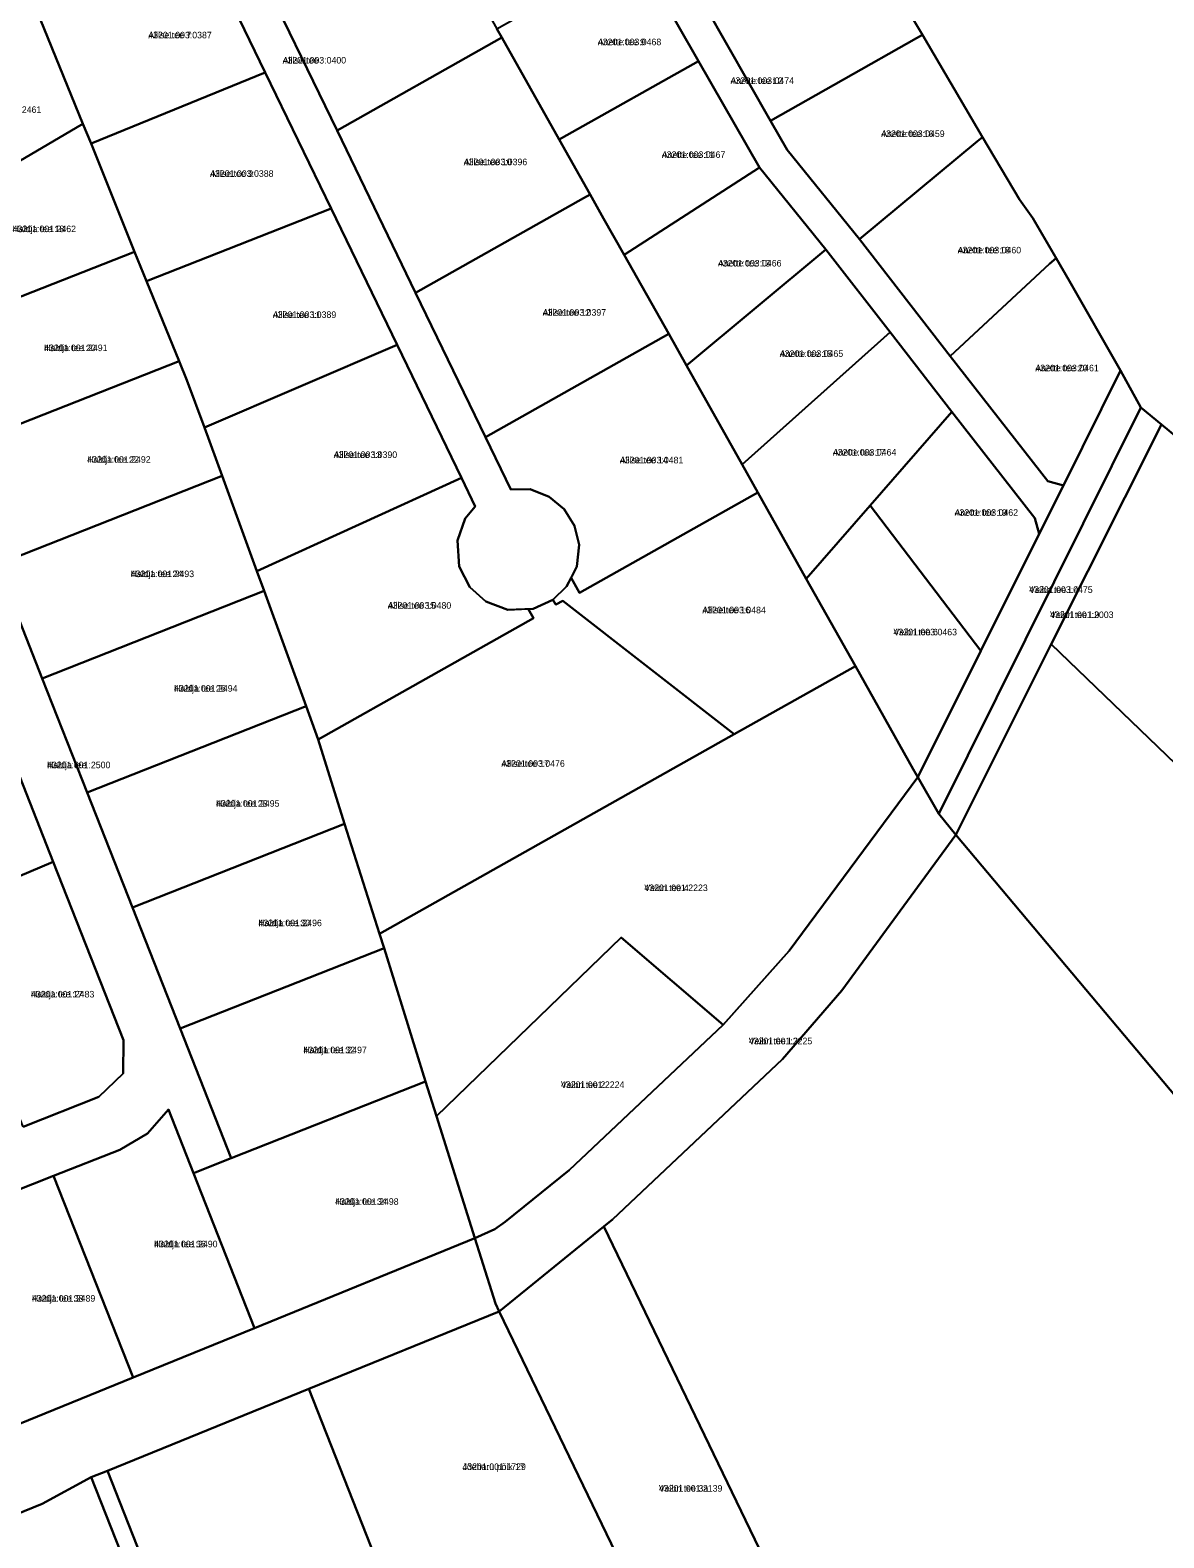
# Model space of a CAD drawing. Extents: x 661852 to 683758, y 6469495 to 6482657.
# Drawn here: x 663455 to 663714.1, y 6470005.7 to 6470350.3 of the extents above; entities that cross this region are included whole.
import ezdxf

# ---------------------------------------------------------------- set-up
doc = ezdxf.new("R2010")
doc.units = 0
for name, color, linetype in [('L_AADRESS', 7, 'Continuous'), ('PIIR', 7, 'Continuous'), ('TUNNUS', 7, 'Continuous')]:
    doc.layers.add(name, color=color, linetype=linetype)

msp = doc.modelspace()

# ---------------------------------------------------------------- linework, layer by layer
at = {"layer": 'PIIR'}
for points in [[(663551.97, 6470463.36), (663549.87, 6470459.62), (663563.18, 6470436.31), (663579.58, 6470407.67), (663594.36, 6470381.56), (663609.37, 6470355.58), (663624.26, 6470329.54), (663628.03, 6470322.94), (663644.55, 6470302.52), (663665.29, 6470275.78), (663687.59, 6470247.16), (663691.18, 6470246.17), (663685.65, 6470235.14), (663684.65, 6470238.71), (663665.72, 6470263.06), (663651.61, 6470281.22), (663636.88, 6470300.17), (663621.72, 6470318.87), (663607.79, 6470343.17), (663593.4, 6470368.36), (663579.26, 6470393.1), (663564.86, 6470418.28), (663551.46, 6470441.72), (663539.03, 6470463.45)], [(663506.1, 6470366.7), (663539.83, 6470385.7), (663541.42, 6470386.6), (663547.74, 6470375.39), (663561.73, 6470350.56), (663562.85, 6470348.57), (663561.11, 6470347.58), (663525.17, 6470327.33)], [(663643.69, 6470375.01), (663654.36, 6470356.98), (663658.96, 6470349.18), (663657.6, 6470348.41), (663624.26, 6470329.54), (663609.37, 6470355.58), (663642.33, 6470374.24)], [(663455.55, 6470357.09), (663493.33, 6470372.44), (663508.77, 6470340.56), (663468.95, 6470324.34), (663467.07, 6470328.89)], [(663593.4, 6470368.36), (663607.79, 6470343.17), (663577.71, 6470326.26), (663575.97, 6470325.28), (663562.85, 6470348.57), (663561.73, 6470350.56), (663563.48, 6470351.54)], [(663413.86, 6470306.25), (663405.06, 6470316.93), (663438.2, 6470348.65), (663453.21, 6470363), (663455.55, 6470357.09), (663467.07, 6470328.89), (663417.42, 6470299.67)], [(663525.17, 6470327.33), (663561.11, 6470347.58), (663562.85, 6470348.57), (663575.97, 6470325.28), (663583.04, 6470312.73), (663581.47, 6470311.85), (663543.13, 6470290.24)], [(663658.96, 6470349.18), (663672.73, 6470325.82), (663671.58, 6470324.87), (663644.55, 6470302.52), (663628.03, 6470322.94), (663624.26, 6470329.54), (663657.6, 6470348.41)], [(663607.79, 6470343.17), (663621.72, 6470318.87), (663590.81, 6470298.94), (663586.04, 6470307.23), (663583.04, 6470312.73), (663575.97, 6470325.28), (663577.71, 6470326.26)], [(663478.9, 6470299.63), (663468.95, 6470324.34), (663508.77, 6470340.56), (663523.81, 6470309.49), (663481.61, 6470292.92)], [(663424.41, 6470286.73), (663417.42, 6470299.67), (663467.07, 6470328.89), (663468.95, 6470324.34), (663478.9, 6470299.63), (663427.33, 6470279.31)], [(663672.73, 6470325.82), (663681.15, 6470311.54), (663684.21, 6470307.28), (663689.5, 6470298.18), (663688.03, 6470296.82), (663665.29, 6470275.78), (663644.55, 6470302.52), (663671.58, 6470324.87)], [(663621.72, 6470318.87), (663636.88, 6470300.17), (663605.06, 6470273.63), (663601.01, 6470280.83), (663590.81, 6470298.94)], [(663543.13, 6470290.24), (663581.47, 6470311.85), (663583.04, 6470312.73), (663586.04, 6470307.23), (663590.81, 6470298.94), (663601.01, 6470280.83), (663559.1, 6470257.26)], [(663489.08, 6470274.65), (663481.61, 6470292.92), (663523.81, 6470309.49), (663538.9, 6470278.33), (663494.85, 6470259.49), (663490.85, 6470270.27)], [(663437.22, 6470254.19), (663427.33, 6470279.31), (663478.9, 6470299.63), (663481.61, 6470292.92), (663489.08, 6470274.65)], [(663636.88, 6470300.17), (663651.61, 6470281.22), (663617.77, 6470251.01), (663605.06, 6470273.63)], [(663689.5, 6470298.18), (663692.54, 6470292.88), (663704.26, 6470272.48), (663691.18, 6470246.17), (663687.59, 6470247.16), (663665.29, 6470275.78), (663688.03, 6470296.82)], [(663559.1, 6470257.26), (663601.01, 6470280.83), (663605.06, 6470273.63), (663617.77, 6470251.01), (663621.37, 6470244.61), (663580.57, 6470221.67), (663578.65, 6470225.07), (663579.97, 6470227.66), (663580.5, 6470232.6), (663579.46, 6470236.96), (663577.11, 6470240.76), (663573.66, 6470243.64), (663569.28, 6470245.33), (663564.89, 6470245.32)], [(663651.61, 6470281.22), (663665.72, 6470263.06), (663647, 6470241.61), (663632.41, 6470224.85), (663621.37, 6470244.61), (663617.77, 6470251.01)], [(663498.91, 6470248.41), (663494.85, 6470259.49), (663538.9, 6470278.33), (663553.63, 6470247.92), (663506.83, 6470226.65)], [(663447.51, 6470228.15), (663437.22, 6470254.19), (663489.08, 6470274.65), (663490.85, 6470270.27), (663494.85, 6470259.49), (663498.91, 6470248.41)], [(663704.26, 6470272.48), (663708.85, 6470264.03), (663662.69, 6470171.12), (663657.88, 6470179.51), (663672.32, 6470208.4), (663685.65, 6470235.14), (663691.18, 6470246.17)], [(663666.62, 6470166.36), (663662.69, 6470171.12), (663708.85, 6470264.03), (663713.6, 6470260.11), (663688.4, 6470209.95)], [(663665.72, 6470263.06), (663684.65, 6470238.71), (663685.65, 6470235.14), (663672.32, 6470208.4), (663647, 6470241.61)], [(663769.59, 6470131.79), (663688.4, 6470209.95), (663713.6, 6470260.11), (663813.93, 6470177.18)], [(663457.77, 6470202.1), (663447.51, 6470228.15), (663498.91, 6470248.41), (663506.83, 6470226.65), (663508.52, 6470222.1)], [(663518.08, 6470195.78), (663508.52, 6470222.1), (663506.83, 6470226.65), (663553.63, 6470247.92), (663556.77, 6470241.43), (663554.46, 6470238.68), (663552.68, 6470233.66), (663553.08, 6470227.72), (663555.53, 6470222.94), (663559.19, 6470219.67), (663564.2, 6470217.79), (663568.87, 6470217.99), (663570.06, 6470215.88), (663520.86, 6470188.15)], [(663578.65, 6470225.07), (663580.57, 6470221.67), (663621.37, 6470244.61), (663632.41, 6470224.85), (663643.63, 6470204.94), (663615.9, 6470189.37), (663576.81, 6470219.87), (663575.2, 6470218.97), (663574.46, 6470220.06), (663577.64, 6470223.08)], [(663632.41, 6470224.85), (663647, 6470241.61), (663672.32, 6470208.4), (663657.88, 6470179.51), (663656.82, 6470181.37), (663643.63, 6470204.94)], [(663468.04, 6470176.05), (663457.77, 6470202.1), (663508.52, 6470222.1), (663518.08, 6470195.78)], [(663526.91, 6470168.89), (663520.86, 6470188.15), (663570.06, 6470215.88), (663568.87, 6470217.99), (663570.02, 6470218.04), (663574.46, 6470220.06), (663575.2, 6470218.97), (663576.81, 6470219.87), (663615.9, 6470189.37), (663534.85, 6470143.76)], [(663434, 6470149.07), (663414.54, 6470198.48), (663441.1, 6470208.95), (663460.32, 6470160.22)], [(663547.9, 6470102.06), (663545.42, 6470109.96), (663535.91, 6470140.42), (663534.85, 6470143.76), (663615.9, 6470189.37), (663643.63, 6470204.94), (663656.82, 6470181.37), (663657.88, 6470179.51), (663628.53, 6470139.84), (663613.39, 6470122.91), (663590.14, 6470142.86)], [(663478.4, 6470149.77), (663468.04, 6470176.05), (663518.08, 6470195.78), (663520.86, 6470188.15), (663526.91, 6470168.89)], [(663558.1, 6470069.62), (663556.66, 6470074.15), (663561.21, 6470076.23), (663563.62, 6470077.94), (663578.24, 6470089.74), (663613.39, 6470122.91), (663628.53, 6470139.84), (663657.88, 6470179.51), (663662.69, 6470171.12), (663666.62, 6470166.36), (663640.51, 6470130.78), (663626.98, 6470115.12), (663588.15, 6470078.45), (663586.13, 6470076.83), (663562.22, 6470057.44), (663561.41, 6470059.24)], [(663489.34, 6470122.06), (663478.4, 6470149.77), (663526.91, 6470168.89), (663534.85, 6470143.76), (663535.91, 6470140.42)], [(663635.28, 6469975), (663586.13, 6470076.83), (663588.15, 6470078.45), (663626.98, 6470115.12), (663640.51, 6470130.78), (663666.62, 6470166.36), (663903.55, 6469884.47), (663665.66, 6469842.51), (663643.63, 6469888.36), (663626.47, 6469924.05), (663607.84, 6469962.97)], [(663453.46, 6470099.65), (663434, 6470149.07), (663460.32, 6470160.22), (663476.4, 6470119.44), (663476.27, 6470111.79), (663470.76, 6470106.47)], [(663556.66, 6470074.15), (663547.9, 6470102.06), (663590.14, 6470142.86), (663613.39, 6470122.91), (663578.24, 6470089.74), (663563.62, 6470077.94), (663561.21, 6470076.23)], [(663501.01, 6470092.46), (663489.34, 6470122.06), (663535.91, 6470140.42), (663545.42, 6470109.96)], [(663506.34, 6470053.64), (663492.37, 6470089.05), (663501.01, 6470092.46), (663545.42, 6470109.96), (663547.9, 6470102.06), (663556.66, 6470074.15)], [(663478.56, 6470042.34), (663460.38, 6470088.4), (663475.53, 6470094.38), (663481.82, 6470098.11), (663486.62, 6470103.62), (663492.37, 6470089.05), (663506.34, 6470053.64)], [(663450.57, 6470030.92), (663432.28, 6470077.32), (663460.38, 6470088.4), (663478.56, 6470042.34)], [(663562.22, 6470057.44), (663586.13, 6470076.83), (663635.28, 6469975), (663607.84, 6469962.97), (663588.91, 6470002.16)], [(663540.99, 6469983.29), (663518.75, 6470039.77), (663562.22, 6470057.44), (663588.91, 6470002.16), (663555.63, 6469989.06)], [(663494.75, 6469965.09), (663472.72, 6470021.03), (663518.75, 6470039.77), (663540.99, 6469983.29)], [(663442.36, 6469969.84), (663429.7, 6470002), (663457.78, 6470013.44), (663469.01, 6470019.52), (663482.37, 6469985.59)]]:
    msp.add_lwpolyline(points, close=True, dxfattribs=at)
for points in [[(663506.1, 6470366.7), (663525.17, 6470327.33), (663543.13, 6470290.24), (663559.1, 6470257.26), (663564.89, 6470245.32), (663569.28, 6470245.33), (663573.66, 6470243.64), (663577.11, 6470240.76), (663579.46, 6470236.96), (663580.5, 6470232.6), (663579.97, 6470227.66), (663577.64, 6470223.08), (663574.46, 6470220.06), (663570.02, 6470218.04), (663564.2, 6470217.79), (663559.19, 6470219.67), (663555.53, 6470222.94), (663553.08, 6470227.72), (663552.68, 6470233.66), (663554.46, 6470238.68), (663556.77, 6470241.43), (663553.63, 6470247.92), (663538.9, 6470278.33), (663523.81, 6470309.49), (663508.77, 6470340.56), (663493.33, 6470372.44)], [(663813.93, 6470177.18), (663713.6, 6470260.11), (663708.85, 6470264.03), (663704.26, 6470272.48), (663692.54, 6470292.88), (663689.5, 6470298.18), (663684.21, 6470307.28), (663681.15, 6470311.54), (663672.73, 6470325.82), (663658.96, 6470349.18), (663654.36, 6470356.98)], [(663447.51, 6470228.15), (663457.77, 6470202.1), (663468.04, 6470176.05), (663478.4, 6470149.77), (663489.34, 6470122.06), (663501.01, 6470092.46), (663492.37, 6470089.05), (663486.62, 6470103.62), (663481.82, 6470098.11), (663475.53, 6470094.38), (663460.38, 6470088.4), (663432.28, 6470077.32)], [(663453.46, 6470099.65), (663470.76, 6470106.47), (663476.27, 6470111.79), (663476.4, 6470119.44), (663460.32, 6470160.22), (663441.1, 6470208.95)], [(663903.55, 6469884.47), (663666.62, 6470166.36), (663688.4, 6470209.95), (663769.59, 6470131.79)], [(663382.98, 6470003.39), (663410.76, 6470014.71), (663424.13, 6470020.15), (663450.57, 6470030.92), (663478.56, 6470042.34), (663506.34, 6470053.64), (663556.66, 6470074.15), (663558.1, 6470069.62), (663561.41, 6470059.24), (663562.22, 6470057.44), (663518.75, 6470039.77), (663472.72, 6470021.03), (663469.01, 6470019.52), (663457.78, 6470013.44), (663429.7, 6470002)], [(663482.37, 6469985.59), (663469.01, 6470019.52), (663472.72, 6470021.03), (663494.75, 6469965.09)]]:
    msp.add_lwpolyline(points, dxfattribs=at)

# ---------------------------------------------------------------- texts
at = {"layer": 'L_AADRESS'}
for s, p in [('Aliise tee 7', (663482.04, 6470348.39)), ('Anette tee 9', (663584.77, 6470346.82)), ('Aliise tee', (663512.75, 6470342.64)), ('Anette tee L2', (663615.11, 6470337.98)), ('Anette tee 16', (663649.54, 6470325.85)), ('Anette tee 11', (663599.41, 6470321.06)), ('Aliise tee 10', (663554.14, 6470319.4)), ('Aliise tee 9', (663496.16, 6470316.74)), ('Haldja tee 18', (663451.02, 6470304.1)), ('Anette tee 18', (663667.02, 6470299.24)), ('Anette tee 13', (663612.25, 6470296.25)), ('Aliise tee 11', (663510.49, 6470284.49)), ('Aliise tee 12', (663572.17, 6470285)), ('Haldja tee 20', (663458.22, 6470276.91)), ('Anette tee 15', (663626.36, 6470275.59)), ('Anette tee 20', (663684.77, 6470272.29)), ('Aliise tee 13', (663524.42, 6470252.49)), ('Anette tee 17', (663638.5, 6470253.04)), ('Haldja tee 22', (663468.07, 6470251.4)), ('Aliise tee 14', (663589.82, 6470251.25)), ('Anette tee 19', (663666.32, 6470239.27)), ('Haldja tee 24', (663478, 6470225.26)), ('Veibri tee L4', (663683.37, 6470221.65)), ('Aliise tee 15', (663536.77, 6470218.04)), ('Aliise tee 16', (663608.67, 6470216.99)), ('Veibri tee L9', (663688.14, 6470215.9)), ('Veibri tee 6', (663652.36, 6470211.95)), ('Haldja tee 26', (663487.92, 6470199.08)), ('Haldja tee', (663458.88, 6470181.58)), ('Aliise tee 17', (663562.73, 6470181.91)), ('Haldja tee 28', (663497.51, 6470172.78)), ('Veibri tee 4', (663595.4, 6470153.5)), ('Haldja tee 30', (663507.2, 6470145.48)), ('Haldja tee 17', (663455.2, 6470129.19)), ('Veibri tee L3', (663619.28, 6470118.48)), ('Haldja tee 32', (663517.48, 6470116.44)), ('Veibri tee 2', (663576.35, 6470108.5)), ('Haldja tee 34', (663524.74, 6470081.8)), ('Haldja tee 36', (663483.36, 6470072.09)), ('Haldja tee 38', (663455.42, 6470059.67)), ('Jõeharu põik 17', (663553.83, 6470021.19)), ('Veibri tee 3a', (663598.75, 6470016.24))]:
    msp.add_text(s, height=1.5, dxfattribs=at).set_placement(p)
at = {"layer": 'TUNNUS'}
for s, p in [('43201:003:0387', (663482.04, 6470348.39)), ('43201:003:0468', (663584.77, 6470346.82)), ('43201:003:0400', (663512.75, 6470342.64)), ('43201:003:0474', (663615.11, 6470337.98)), ('43201:001:2461', (663443.09, 6470331.34)), ('43201:003:0459', (663649.54, 6470325.85)), ('43201:003:0467', (663599.41, 6470321.06)), ('43201:003:0396', (663554.14, 6470319.4)), ('43201:003:0388', (663496.16, 6470316.74)), ('43201:001:2462', (663451.02, 6470304.1)), ('43201:003:0460', (663667.02, 6470299.24)), ('43201:003:0466', (663612.25, 6470296.25)), ('43201:003:0389', (663510.49, 6470284.49)), ('43201:003:0397', (663572.17, 6470285)), ('43201:001:2491', (663458.22, 6470276.91)), ('43201:003:0465', (663626.36, 6470275.59)), ('43201:003:0461', (663684.77, 6470272.29)), ('43201:003:0390', (663524.42, 6470252.49)), ('43201:003:0464', (663638.5, 6470253.04)), ('43201:001:2492', (663468.07, 6470251.4)), ('43201:003:0481', (663589.82, 6470251.25)), ('43201:003:0462', (663666.32, 6470239.27)), ('43201:001:2493', (663478, 6470225.26)), ('43201:003:0475', (663683.37, 6470221.65)), ('43201:003:0480', (663536.77, 6470218.04)), ('43201:003:0484', (663608.67, 6470216.99)), ('43201:001:2003', (663688.14, 6470215.9)), ('43201:003:0463', (663652.36, 6470211.95)), ('43201:001:2494', (663487.92, 6470199.08)), ('43201:001:2500', (663458.88, 6470181.58)), ('43201:003:0476', (663562.73, 6470181.91)), ('43201:001:2495', (663497.51, 6470172.78)), ('43201:001:2223', (663595.4, 6470153.5)), ('43201:001:2496', (663507.2, 6470145.48)), ('43201:001:2483', (663455.2, 6470129.19)), ('43201:001:2225', (663619.28, 6470118.48)), ('43201:001:2497', (663517.48, 6470116.44)), ('43201:001:2224', (663576.35, 6470108.5)), ('43201:001:2498', (663524.74, 6470081.8)), ('43201:001:2490', (663483.36, 6470072.09)), ('43201:001:2489', (663455.42, 6470059.67)), ('43201:001:1729', (663553.83, 6470021.19)), ('43201:001:2139', (663598.75, 6470016.24))]:
    msp.add_text(s, height=1.5, dxfattribs=at).set_placement(p)

doc.saveas('drawing.dxf')
